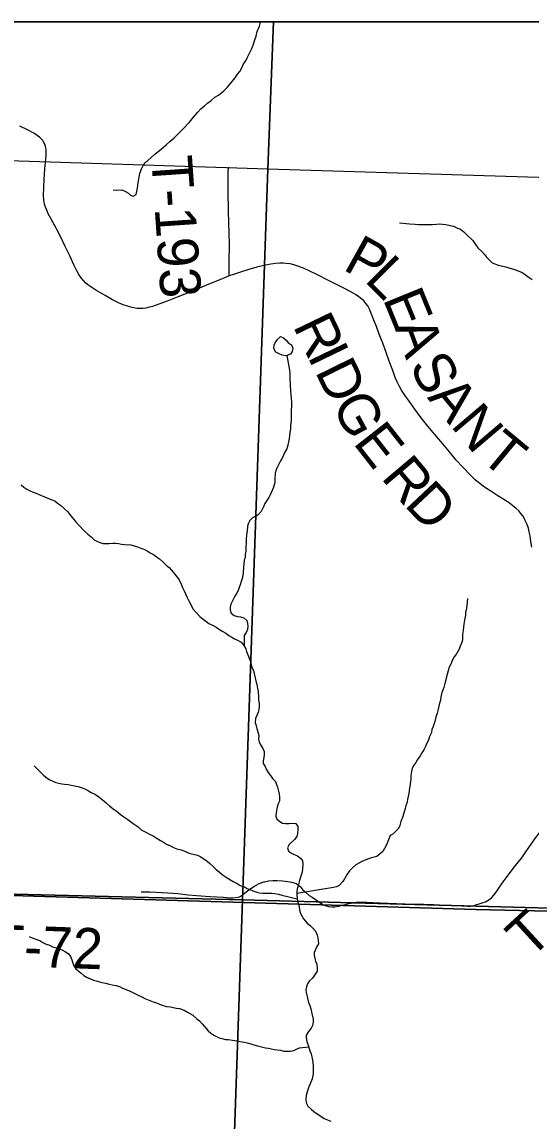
# Model space of a CAD drawing. Extents: x -3.3 to 34, y 0 to 56.8.
# Drawn here: x -0.562 to 0.148, y 33.346 to 34.877 of the extents above; entities that cross this region are included whole.
import ezdxf

# ---------------------------------------------------------------- set-up
doc = ezdxf.new("R2010")
doc.units = 0
for name, color, linetype in [('GM_X_Corporation', 7, 'Continuous'), ('GM_X_County_Road', 7, 'Continuous'), ('GM_X_Township_Road', 7, 'Continuous'), ('GM_X_Township_Road_Text', 7, 'Continuous'), ('GT_Project_Soil_Layers', 7, 'Continuous'), ('SH_Data', 7, 'Continuous'), ('SH_Masking', 7, 'Continuous')]:
    doc.layers.add(name, color=color, linetype=linetype)

msp = doc.modelspace()

# ---------------------------------------------------------------- linework, layer by layer
at = {"layer": 'GM_X_Corporation'}
for points in [[(1.8402, 34.8771), (-3.3039, 34.8771), (-3.3039, 33.7379), (-1.9559, 33.6976), (-1.4178, 33.6828), (-1.3158, 33.6798), (-1.2647, 33.6785), (-1.2619, 33.6785), (-1.2559, 33.6783), (-1.2477, 33.6781), (-0.684, 33.6635), (0.0711, 33.6404), (0.5386, 33.6297), (1.1691, 33.6097), (1.268, 33.607), (1.3813, 33.6045), (1.3939, 33.6042), (1.4033, 33.604), (1.5156, 33.6018), (1.5452, 33.6012), (1.798, 33.5922), (1.8165, 34.1713), (1.8337, 34.7226), (1.8394, 34.8565)], [(-0.2111, 34.8771), (-1.2253, 34.8771), (-1.231, 34.705), (-0.2186, 34.6726)], [(0.815, 34.8771), (-0.2111, 34.8771), (-0.2186, 34.6726), (0.8071, 34.6408)], [(-1.231, 34.705), (-0.2186, 34.6726), (-0.2543, 33.6541), (-1.2628, 33.6793)], [(0.8071, 34.6408), (0.7743, 33.6261), (-0.2543, 33.6541), (-0.2186, 34.6726)], [(-1.2628, 33.6793), (-0.2543, 33.6541), (-0.2878, 32.6826), (-1.3017, 32.7146)], [(-0.2543, 33.6541), (0.7743, 33.6261), (0.7357, 32.6242), (-0.2878, 32.6826)]]:
    msp.add_lwpolyline(points, close=True, dxfattribs=at)
msp.add_lwpolyline([(1.698, 31.5661), (1.7459, 32.363), (1.7461, 32.3685), (1.7485, 32.4264), (1.7493, 32.4459), (1.7554, 32.5941), (1.7581, 32.6599), (1.7584, 32.6672), (1.7602, 32.7115), (1.7831, 33.2694), (1.7901, 33.4394), (1.798, 33.5922), (1.5452, 33.6012), (1.5156, 33.6018), (1.4033, 33.604), (1.3939, 33.6042), (1.3813, 33.6045), (1.268, 33.607), (1.1691, 33.6097), (0.5386, 33.6297), (0.0711, 33.6404), (-0.684, 33.6635)], dxfattribs=at)
at = {"layer": 'GM_X_County_Road'}
msp.add_lwpolyline([(0.1491, 34.1456), (0.1479, 34.1532), (0.1467, 34.1613), (0.1456, 34.1667), (0.1443, 34.172), (0.1422, 34.1778), (0.14, 34.1827), (0.1384, 34.1859), (0.1365, 34.1891), (0.134, 34.1923), (0.1309, 34.1959), (0.1269, 34.1998), (0.1227, 34.2031), (0.1178, 34.2068), (0.1123, 34.2105), (0.1019, 34.217), (0.0932, 34.2225), (0.0883, 34.2256), (0.0817, 34.2299), (0.0767, 34.2339), (0.0708, 34.2387), (0.0675, 34.2418), (0.0637, 34.2456), (0.0534, 34.2563), (0.0439, 34.2668), (0.0342, 34.2782), (0.025, 34.2892), (0.0141, 34.3023), (0.0043, 34.314), (-0.0049, 34.3257), (-0.0141, 34.3376), (-0.0218, 34.3487), (-0.0277, 34.3571), (-0.0323, 34.3641), (-0.0354, 34.3693), (-0.0386, 34.3755), (-0.0411, 34.3818), (-0.0448, 34.3913), (-0.0495, 34.4044), (-0.0545, 34.4182), (-0.0586, 34.4295), (-0.0635, 34.4423), (-0.0675, 34.4527), (-0.071, 34.4618), (-0.0743, 34.4702), (-0.0771, 34.4768), (-0.0795, 34.4814), (-0.082, 34.4849), (-0.085, 34.4884), (-0.0879, 34.491), (-0.0918, 34.4941), (-0.0964, 34.4972), (-0.103, 34.5011), (-0.113, 34.5061), (-0.124, 34.5116), (-0.1354, 34.5174), (-0.1498, 34.5246), (-0.1614, 34.5304), (-0.1693, 34.5339), (-0.1782, 34.5374), (-0.1824, 34.5388), (-0.1876, 34.5399), (-0.1931, 34.5407), (-0.1976, 34.5409), (-0.2021, 34.541), (-0.2083, 34.5406), (-0.2144, 34.5398), (-0.2244, 34.5379), (-0.234, 34.5356), (-0.2453, 34.5323), (-0.2567, 34.5287), (-0.2668, 34.5253), (-0.2729, 34.5233), (-0.2858, 34.5179), (-0.3032, 34.5107), (-0.3214, 34.5031), (-0.3343, 34.4979), (-0.3453, 34.4935), (-0.3591, 34.4882), (-0.3707, 34.4837), (-0.3796, 34.4806), (-0.3854, 34.4792), (-0.389, 34.4784), (-0.3932, 34.4779), (-0.3969, 34.4777), (-0.4013, 34.478), (-0.408, 34.4792), (-0.4146, 34.481), (-0.4204, 34.4831), (-0.4271, 34.4859), (-0.4353, 34.49), (-0.4457, 34.496), (-0.4586, 34.5035), (-0.4643, 34.507), (-0.467, 34.5089), (-0.4696, 34.5109), (-0.4724, 34.5134), (-0.4757, 34.5168), (-0.4788, 34.5206), (-0.4821, 34.5254), (-0.4848, 34.5302), (-0.489, 34.5386), (-0.4944, 34.5503), (-0.5012, 34.5643), (-0.5074, 34.5771), (-0.5135, 34.5888), (-0.5214, 34.6033), (-0.5248, 34.6098), (-0.527, 34.6148), (-0.5287, 34.6192), (-0.53, 34.6233), (-0.5306, 34.6262), (-0.5309, 34.629), (-0.5313, 34.6351), (-0.5306, 34.6575), (-0.5297, 34.6724), (-0.5289, 34.6818), (-0.5279, 34.6909), (-0.5276, 34.6941), (-0.5277, 34.6971), (-0.528, 34.7), (-0.5288, 34.7036), (-0.5297, 34.7066), (-0.531, 34.7091), (-0.5326, 34.7118), (-0.5348, 34.7144), (-0.5372, 34.7166), (-0.5403, 34.719), (-0.545, 34.7221), (-0.5536, 34.7268), (-0.5643, 34.7321)], dxfattribs=at)
at = {"layer": 'GM_X_Township_Road'}
for points in [[(-0.2729, 34.5233), (-0.2726, 34.5426), (-0.2723, 34.5669), (-0.2726, 34.583), (-0.2733, 34.5979), (-0.2737, 34.6134), (-0.2739, 34.6416), (-0.2742, 34.6546), (-0.2742, 34.6625), (-0.2739, 34.6687), (-0.2732, 34.6747)], [(0.1397, 33.7195), (0.1449, 33.7272), (0.1547, 33.7407), (0.1599, 33.7473), (0.1638, 33.7533), (0.1682, 33.762), (0.1728, 33.7722), (0.1768, 33.7826), (0.1803, 33.7963), (0.183, 33.8094), (0.1886, 33.8493), (0.19, 33.8606), (0.1907, 33.8735), (0.1885, 33.9027), (0.1883, 33.9138), (0.1884, 33.9205), (0.1911, 33.9428), (0.1926, 33.9538), (0.1946, 33.9635), (0.1959, 33.9682), (0.1984, 33.9753)], [(0.0709, 33.6469), (0.0756, 33.6484), (0.0811, 33.6502), (0.0847, 33.6515), (0.0871, 33.6528), (0.0893, 33.6542), (0.0912, 33.6555), (0.0936, 33.6575), (0.0959, 33.6599), (0.0996, 33.6649), (0.1052, 33.6731), (0.1091, 33.6792), (0.1146, 33.6865), (0.1266, 33.7018), (0.1351, 33.7127), (0.1397, 33.7195)], [(-0.2559, 33.6597), (-0.2538, 33.6613), (-0.2494, 33.6647), (-0.2451, 33.6682), (-0.2374, 33.6733), (-0.2311, 33.6766), (-0.2245, 33.679)], [(-0.2245, 33.679), (-0.2235, 33.6793), (-0.2177, 33.6805), (-0.2117, 33.681), (-0.206, 33.6808), (-0.1984, 33.6803), (-0.1878, 33.6791), (-0.184, 33.6784), (-0.1795, 33.6767), (-0.176, 33.6745), (-0.1734, 33.6721), (-0.1703, 33.6686), (-0.167, 33.6653), (-0.161, 33.6603), (-0.1572, 33.6576), (-0.1524, 33.6545)], [(-0.3954, 33.6654), (-0.3834, 33.665), (-0.3581, 33.664), (-0.3514, 33.6635), (-0.3443, 33.6628), (-0.3298, 33.6612), (-0.3184, 33.6601), (-0.299, 33.6588), (-0.2805, 33.6576), (-0.2721, 33.6569), (-0.2675, 33.657), (-0.2635, 33.6574), (-0.2599, 33.6579), (-0.2566, 33.6591), (-0.2559, 33.6597)], [(-0.1524, 33.6545), (-0.1463, 33.6505), (-0.1411, 33.6473), (-0.1377, 33.6458), (-0.1341, 33.6449), (-0.1294, 33.6442), (-0.1252, 33.6444), (-0.1205, 33.6452), (-0.116, 33.6463), (-0.1054, 33.6491), (-0.1031, 33.6496), (-0.0956, 33.6507), (-0.0921, 33.6509), (-0.0913, 33.6509)], [(-0.0913, 33.6509), (-0.0881, 33.651), (-0.0806, 33.6506), (-0.0629, 33.6499), (-0.0393, 33.6489), (-0.0273, 33.6484), (-0.0157, 33.648), (-0.0014, 33.6478), (0.0127, 33.6476), (0.0285, 33.6468), (0.041, 33.6461), (0.052, 33.6456), (0.0597, 33.6452), (0.0639, 33.6453), (0.0672, 33.6457), (0.07, 33.6466), (0.0709, 33.6469)]]:
    msp.add_lwpolyline(points, dxfattribs=at)
at = {"layer": 'GT_Project_Soil_Layers'}
for points in [[(-0.4346, 34.6432), (-0.43, 34.6429), (-0.4221, 34.643), (-0.4183, 34.6412), (-0.4145, 34.6397), (-0.4102, 34.636), (-0.4064, 34.6342), (-0.4023, 34.6365), (-0.4012, 34.6411), (-0.4005, 34.6456), (-0.4002, 34.6498), (-0.3991, 34.6559), (-0.397, 34.6658), (-0.3948, 34.6723), (-0.3926, 34.6769), (-0.39, 34.6807), (-0.3821, 34.688), (-0.3761, 34.693), (-0.3716, 34.6965), (-0.3675, 34.7), (-0.3607, 34.7058), (-0.3555, 34.7104), (-0.3499, 34.715), (-0.345, 34.7197), (-0.3413, 34.7235), (-0.3375, 34.7277), (-0.3282, 34.7374), (-0.3226, 34.7443), (-0.3162, 34.7516), (-0.3121, 34.7562), (-0.3073, 34.7604), (-0.3031, 34.7639), (-0.2979, 34.7678), (-0.2926, 34.7724), (-0.2877, 34.7751), (-0.2802, 34.7813), (-0.275, 34.7863), (-0.2683, 34.794), (-0.2642, 34.7994), (-0.2612, 34.8043), (-0.2579, 34.8082), (-0.2556, 34.8124), (-0.2527, 34.8189), (-0.2497, 34.8227), (-0.2475, 34.8273), (-0.2438, 34.8346), (-0.2412, 34.8399), (-0.2394, 34.8449), (-0.2368, 34.8521), (-0.235, 34.8575), (-0.2336, 34.8636), (-0.2306, 34.8712), (-0.2288, 34.8769), (-0.2287, 34.8771)], [(-0.0351, 34.5973), (-0.0305, 34.5966), (-0.0214, 34.5959), (-0.0135, 34.5953), (-0.0089, 34.595), (-0.004, 34.595), (0.0021, 34.5947), (0.0108, 34.5949), (0.0165, 34.5953), (0.0207, 34.5958), (0.0248, 34.5954), (0.0294, 34.5947), (0.0355, 34.5933), (0.04, 34.5926), (0.0454, 34.59), (0.0496, 34.5882), (0.0542, 34.5845), (0.058, 34.5811), (0.0669, 34.5725), (0.0707, 34.5672), (0.0738, 34.5623), (0.0796, 34.5571), (0.0834, 34.553), (0.0861, 34.5492), (0.0938, 34.5417), (0.0976, 34.5403), (0.1022, 34.5384), (0.1129, 34.5359), (0.117, 34.5345), (0.122, 34.533), (0.1262, 34.5316), (0.13, 34.5305), (0.1357, 34.5279), (0.1399, 34.5253), (0.1441, 34.5219), (0.1495, 34.5182)], [(-0.1937, 34.4121), (-0.1987, 34.4127), (-0.2032, 34.4146), (-0.2078, 34.4172), (-0.2106, 34.4221), (-0.2102, 34.4266), (-0.208, 34.4308), (-0.205, 34.435), (-0.2013, 34.4389), (-0.1971, 34.4371), (-0.1933, 34.4337), (-0.1898, 34.4296), (-0.186, 34.4273), (-0.184, 34.4228), (-0.1851, 34.4182), (-0.1873, 34.4144), (-0.1937, 34.4121)], [(-0.1923, 34.4126), (-0.1906, 34.4022), (-0.1894, 34.3969), (-0.1885, 34.392), (-0.1881, 34.3871), (-0.188, 34.3791), (-0.1875, 34.373), (-0.1874, 34.3624), (-0.1869, 34.3586), (-0.1865, 34.3526), (-0.186, 34.3472), (-0.1859, 34.3408), (-0.1863, 34.337), (-0.1862, 34.3283), (-0.1864, 34.3222), (-0.1871, 34.3142), (-0.1874, 34.3096), (-0.1881, 34.3051), (-0.1888, 34.3009), (-0.1891, 34.2963), (-0.1898, 34.2921), (-0.1909, 34.2876), (-0.1924, 34.2822), (-0.1949, 34.2776), (-0.1968, 34.2734), (-0.199, 34.2696), (-0.2012, 34.2658), (-0.2053, 34.2574), (-0.2071, 34.2532), (-0.2086, 34.2486), (-0.2092, 34.2399), (-0.2092, 34.2353), (-0.211, 34.2288), (-0.2128, 34.2242), (-0.2154, 34.2185), (-0.2176, 34.2147), (-0.2228, 34.2063), (-0.225, 34.2017), (-0.2283, 34.1952), (-0.2324, 34.1902), (-0.2366, 34.1882), (-0.2403, 34.1863), (-0.2437, 34.1824), (-0.2459, 34.1786), (-0.247, 34.1748), (-0.2477, 34.1679), (-0.2484, 34.163), (-0.249, 34.1554), (-0.249, 34.1508), (-0.2493, 34.1463), (-0.2496, 34.1398), (-0.2503, 34.1353), (-0.2506, 34.1311), (-0.2517, 34.1273), (-0.2524, 34.1223), (-0.2527, 34.1174), (-0.2533, 34.1094), (-0.254, 34.1029), (-0.2562, 34.0976), (-0.2576, 34.093), (-0.2587, 34.0892), (-0.2602, 34.085), (-0.2624, 34.0808), (-0.2646, 34.077), (-0.2672, 34.0724), (-0.2706, 34.0659), (-0.2713, 34.0617), (-0.2712, 34.0579), (-0.27, 34.0533), (-0.2658, 34.05), (-0.2612, 34.0489), (-0.2567, 34.0482), (-0.2521, 34.0468), (-0.2483, 34.043), (-0.2471, 34.0392), (-0.2466, 34.0354), (-0.2473, 34.0309), (-0.2488, 34.0267), (-0.2518, 34.0225), (-0.2518, 34.0076)], [(-0.5625, 34.2322), (-0.5587, 34.2289), (-0.5548, 34.2262), (-0.5503, 34.224), (-0.5457, 34.2222), (-0.5415, 34.2204), (-0.5358, 34.2178), (-0.5308, 34.216), (-0.5247, 34.2134), (-0.5209, 34.2119), (-0.5159, 34.2101), (-0.5121, 34.2067), (-0.5079, 34.2038), (-0.5021, 34.1989), (-0.4979, 34.1952), (-0.4952, 34.1914), (-0.4914, 34.1865), (-0.4871, 34.1813), (-0.4833, 34.1768), (-0.474, 34.167), (-0.4698, 34.1633), (-0.4652, 34.1599), (-0.461, 34.1558), (-0.4572, 34.1536), (-0.453, 34.1518), (-0.4484, 34.1507), (-0.4438, 34.1504), (-0.4401, 34.1504), (-0.4351, 34.1509), (-0.4313, 34.1509), (-0.4268, 34.1506), (-0.4226, 34.1495), (-0.4188, 34.1492), (-0.4097, 34.1486), (-0.4006, 34.1457), (-0.3956, 34.1438), (-0.3918, 34.1428), (-0.3872, 34.1405), (-0.383, 34.1376), (-0.3784, 34.135), (-0.3742, 34.132)], [(-0.3742, 34.132), (-0.3696, 34.129), (-0.3646, 34.1245), (-0.36, 34.1197), (-0.3562, 34.1171), (-0.3531, 34.1133), (-0.3489, 34.1084), (-0.3458, 34.1039), (-0.3423, 34.0998), (-0.3396, 34.0937), (-0.3376, 34.0892), (-0.3353, 34.0847), (-0.3337, 34.0805), (-0.3317, 34.0764), (-0.3298, 34.0726), (-0.3282, 34.0688), (-0.3259, 34.0647), (-0.3235, 34.0594), (-0.3135, 34.0489), (-0.3089, 34.0452), (-0.3051, 34.0422), (-0.3009, 34.0389), (-0.2952, 34.0363), (-0.291, 34.0337), (-0.286, 34.0307), (-0.2814, 34.0277), (-0.2772, 34.0255), (-0.273, 34.0225), (-0.2692, 34.0199), (-0.2653, 34.0177), (-0.2611, 34.0159), (-0.2562, 34.0129), (-0.2523, 34.0084), (-0.2496, 34.0039), (-0.2484, 34.0001), (-0.2468, 33.9956), (-0.2449, 33.9907), (-0.2429, 33.9861), (-0.2409, 33.9778), (-0.239, 33.9737), (-0.2378, 33.9695), (-0.2365, 33.9631), (-0.2354, 33.9593), (-0.2341, 33.954), (-0.2333, 33.9487), (-0.2325, 33.9445), (-0.2316, 33.9366), (-0.2316, 33.932), (-0.2311, 33.9278), (-0.2311, 33.9233), (-0.2314, 33.9191), (-0.2321, 33.9153), (-0.2343, 33.9107), (-0.2361, 33.9065), (-0.2365, 33.9012), (-0.2353, 33.8966), (-0.2341, 33.8929), (-0.2313, 33.883), (-0.2316, 33.8781), (-0.2308, 33.8743), (-0.2288, 33.8701), (-0.2257, 33.8649), (-0.2241, 33.8607), (-0.2237, 33.8565), (-0.2244, 33.8524), (-0.2251, 33.8478), (-0.2251, 33.844), (-0.2227, 33.8398), (-0.2212, 33.8361), (-0.2184, 33.8316), (-0.215, 33.8274), (-0.2123, 33.8229), (-0.208, 33.8188), (-0.2065, 33.8146), (-0.2053, 33.8109), (-0.2045, 33.8071), (-0.2032, 33.8018), (-0.2024, 33.7972), (-0.2027, 33.7915), (-0.2042, 33.7877), (-0.2056, 33.7831), (-0.2071, 33.7755), (-0.2078, 33.7706), (-0.2062, 33.7664), (-0.2023, 33.763), (-0.1985, 33.7608), (-0.194, 33.7605), (-0.1894, 33.7606), (-0.1849, 33.761), (-0.1799, 33.7603), (-0.1772, 33.7562), (-0.1768, 33.752), (-0.1775, 33.7463), (-0.1785, 33.7425), (-0.1815, 33.7379), (-0.189, 33.731), (-0.1912, 33.7264), (-0.19, 33.7218), (-0.1858, 33.7192), (-0.182, 33.7174), (-0.1774, 33.7155)], [(0.0596, 34.0739), (0.0589, 34.0686), (0.0586, 34.0644), (0.0579, 34.0606), (0.0568, 34.0545), (0.0565, 34.0507), (0.0551, 34.0439), (0.0544, 34.0382), (0.0537, 34.0344), (0.0534, 34.0294), (0.0523, 34.0237), (0.0524, 34.0157), (0.0513, 34.0115), (0.0495, 34.0073), (0.0477, 34.0035), (0.044, 33.997), (0.041, 33.9924), (0.0388, 33.9886), (0.0362, 33.9825), (0.0336, 33.9775), (0.0325, 33.9729), (0.0307, 33.9664), (0.0296, 33.9623), (0.0282, 33.9573), (0.0264, 33.9501), (0.0238, 33.9428), (0.0224, 33.9371), (0.0217, 33.9318), (0.0203, 33.9279), (0.0195, 33.9241), (0.0181, 33.9177), (0.017, 33.9139), (0.0152, 33.9085), (0.0138, 33.9024), (0.0116, 33.8956), (0.0098, 33.8913), (0.0091, 33.8872), (0.0065, 33.8814), (0.005, 33.8765), (0.0028, 33.8723), (0.001, 33.8677), (-0.0012, 33.8631), (-0.0042, 33.8589), (-0.0064, 33.8547), (-0.0101, 33.8497), (-0.0124, 33.8455), (-0.0153, 33.8416), (-0.0176, 33.8374), (-0.0186, 33.8328), (-0.0193, 33.8275), (-0.0196, 33.8222), (-0.021, 33.8123), (-0.0217, 33.8062), (-0.0224, 33.802), (-0.0238, 33.7963), (-0.0249, 33.7887), (-0.0263, 33.7849), (-0.0274, 33.7811), (-0.0292, 33.775), (-0.031, 33.7689), (-0.0332, 33.7631), (-0.035, 33.7574), (-0.0369, 33.7536), (-0.0403, 33.7498), (-0.0447, 33.7455), (-0.0485, 33.7436), (-0.0503, 33.739), (-0.0514, 33.7352), (-0.0533, 33.7306), (-0.0562, 33.7256), (-0.0584, 33.7214), (-0.0667, 33.7144), (-0.0705, 33.7133), (-0.0742, 33.7124), (-0.0784, 33.7112), (-0.0867, 33.7081), (-0.0912, 33.7057), (-0.0961, 33.7026), (-0.1006, 33.6988), (-0.1051, 33.6945), (-0.1081, 33.6896), (-0.1118, 33.6834), (-0.1144, 33.6796), (-0.1192, 33.6742), (-0.123, 33.6723), (-0.1275, 33.6711), (-0.1786, 33.6627)], [(-0.5443, 33.8406), (-0.5393, 33.8358), (-0.5358, 33.832), (-0.532, 33.8283), (-0.5281, 33.8249), (-0.5235, 33.8219), (-0.5144, 33.8175), (-0.5102, 33.8164), (-0.506, 33.8157), (-0.5022, 33.8154), (-0.4969, 33.8147), (-0.4931, 33.814), (-0.4878, 33.813), (-0.4832, 33.8119), (-0.4775, 33.8101), (-0.4729, 33.8082), (-0.4687, 33.806), (-0.4649, 33.8038), (-0.4599, 33.8012), (-0.4561, 33.799), (-0.45, 33.7945), (-0.4435, 33.7889), (-0.4396, 33.7852), (-0.4343, 33.7807), (-0.4304, 33.7781), (-0.4247, 33.7736), (-0.4197, 33.7699), (-0.414, 33.7658), (-0.4101, 33.7632), (-0.4063, 33.7602), (-0.3994, 33.7557), (-0.3952, 33.7516), (-0.3898, 33.7486), (-0.383, 33.7453), (-0.3788, 33.7431), (-0.3746, 33.7405), (-0.3684, 33.7368), (-0.3642, 33.7346), (-0.36, 33.7316), (-0.3543, 33.7294), (-0.3501, 33.7272), (-0.3455, 33.7253), (-0.3398, 33.7235), (-0.336, 33.7221), (-0.331, 33.7202), (-0.3269, 33.7188), (-0.317, 33.7162), (-0.3124, 33.714), (-0.3036, 33.7081), (-0.2997, 33.7047), (-0.2948, 33.7006), (-0.2913, 33.6969), (-0.2863, 33.6924), (-0.2825, 33.6894), (-0.2756, 33.6849), (-0.2672, 33.6797), (-0.2614, 33.6768), (-0.2576, 33.6742), (-0.2515, 33.672), (-0.2477, 33.6697), (-0.2385, 33.6661), (-0.234, 33.6646), (-0.2302, 33.6639), (-0.226, 33.6632), (-0.2131, 33.6634), (-0.2089, 33.6631), (-0.204, 33.662), (-0.1994, 33.6605), (-0.1778, 33.6556)], [(-0.1774, 33.7155), (-0.1732, 33.7122), (-0.1705, 33.7084), (-0.1701, 33.7043), (-0.1707, 33.6963), (-0.1714, 33.6913), (-0.1729, 33.6871), (-0.1747, 33.681), (-0.1758, 33.6772), (-0.1765, 33.6734), (-0.1779, 33.6696), (-0.1786, 33.6654), (-0.1786, 33.6605), (-0.1773, 33.6521), (-0.1761, 33.6483), (-0.1753, 33.6438), (-0.1741, 33.6377), (-0.1729, 33.634), (-0.169, 33.6276), (-0.164, 33.6215), (-0.1598, 33.6182), (-0.1559, 33.6148), (-0.1525, 33.6103), (-0.1501, 33.605), (-0.1489, 33.6013), (-0.1485, 33.5975), (-0.1484, 33.5929), (-0.1503, 33.5891), (-0.1525, 33.5849), (-0.154, 33.5807), (-0.1543, 33.5769), (-0.1535, 33.5723), (-0.1523, 33.5685), (-0.1507, 33.5644), (-0.1502, 33.5587), (-0.1502, 33.5545), (-0.1528, 33.5503), (-0.1565, 33.5449), (-0.1606, 33.5411), (-0.1636, 33.5372), (-0.1651, 33.533), (-0.1658, 33.5288), (-0.1653, 33.5251), (-0.1645, 33.5213), (-0.1637, 33.5171), (-0.1621, 33.511), (-0.1605, 33.5069), (-0.1589, 33.502), (-0.1573, 33.4959), (-0.1557, 33.4876), (-0.1557, 33.4834), (-0.1567, 33.4792), (-0.1586, 33.4754), (-0.1623, 33.4704), (-0.1653, 33.4654), (-0.1652, 33.4616), (-0.1644, 33.4567), (-0.1624, 33.4514), (-0.1604, 33.4435), (-0.1585, 33.4397), (-0.1569, 33.4329), (-0.156, 33.428), (-0.1556, 33.4219), (-0.1555, 33.4162), (-0.1558, 33.4116), (-0.1568, 33.4048), (-0.1598, 33.3975), (-0.1616, 33.3937), (-0.1631, 33.3895), (-0.1649, 33.3834), (-0.166, 33.3784), (-0.1659, 33.3743), (-0.1647, 33.3705), (-0.1631, 33.3667), (-0.1585, 33.3622), (-0.1547, 33.3592), (-0.1501, 33.3559), (-0.1448, 33.3525), (-0.1402, 33.3495), (-0.131, 33.3455)], [(-0.5516, 33.6028), (-0.5471, 33.601), (-0.5421, 33.5991), (-0.5368, 33.5973), (-0.5326, 33.5947), (-0.5276, 33.5925), (-0.523, 33.5911), (-0.5188, 33.5888), (-0.5135, 33.5874), (-0.5059, 33.5845), (-0.5009, 33.5815), (-0.4971, 33.5793), (-0.494, 33.5751), (-0.492, 33.5706), (-0.4897, 33.563), (-0.4862, 33.5578), (-0.4793, 33.5522), (-0.4751, 33.5488), (-0.4708, 33.5458), (-0.4667, 33.5444), (-0.4617, 33.5422), (-0.4564, 33.5407), (-0.4503, 33.5389), (-0.445, 33.5378), (-0.44, 33.5368), (-0.4358, 33.5357), (-0.4305, 33.5346), (-0.4256, 33.5332), (-0.4214, 33.531), (-0.4107, 33.5266), (-0.4053, 33.524), (-0.3988, 33.521), (-0.3946, 33.5188), (-0.3901, 33.5166), (-0.3855, 33.5148), (-0.3786, 33.5118), (-0.3741, 33.5107), (-0.3699, 33.5089), (-0.366, 33.5074), (-0.36, 33.5056), (-0.3546, 33.5049), (-0.3508, 33.5042), (-0.3463, 33.5031), (-0.3417, 33.5025), (-0.3356, 33.5003), (-0.331, 33.4977), (-0.3234, 33.4932), (-0.318, 33.4884), (-0.3142, 33.4857), (-0.3103, 33.4812), (-0.3069, 33.4775), (-0.3022, 33.4715), (-0.2984, 33.4681), (-0.2942, 33.4655), (-0.2866, 33.4618), (-0.2827, 33.4607), (-0.2778, 33.4597), (-0.274, 33.4593), (-0.2649, 33.458), (-0.2611, 33.4576), (-0.2573, 33.4569), (-0.252, 33.4559), (-0.2478, 33.4548), (-0.2425, 33.4533), (-0.2383, 33.4522), (-0.2333, 33.4508), (-0.2219, 33.4479), (-0.2181, 33.4472), (-0.2135, 33.4465), (-0.2097, 33.4454), (-0.2052, 33.4451), (-0.201, 33.4444), (-0.1964, 33.4433), (-0.1919, 33.443), (-0.1873, 33.4431), (-0.1828, 33.4443), (-0.179, 33.4462), (-0.1749, 33.4478), (-0.1619, 33.4492)]]:
    msp.add_lwpolyline(points, dxfattribs=at)
at = {"layer": 'SH_Data'}
msp.add_line((-3.3039, 34.8771), (3.4961, 34.8771), dxfattribs=at)

# ---------------------------------------------------------------- texts
at = {"layer": 'GM_X_Township_Road_Text'}
for s, height, rotation, p in [('T-193', 0.05682, 273.9259, (-0.3814, 34.689)), ('T', 0.0568, 42.5842, (0.1465, 33.5704)), ('T-72', 0.05682, 357.8787, (-0.6058, 33.563))]:
    msp.add_text(s, height=height, rotation=rotation, dxfattribs=at).set_placement(p)
at = {"layer": 'SH_Masking'}
for s, rotation, p in [('P', 330.8439, (-0.1157, 34.5329)), ('L', 314.8697, (-0.0856, 34.5167)), ('E', 292.189, (-0.0589, 34.4916)), ('R', 295.7516, (-0.1845, 34.4538)), ('A', 290.1493, (-0.043, 34.4527)), ('I', 295.8192, (-0.1642, 34.4117)), ('D', 296.1676, (-0.1538, 34.3904)), ('S', 297.6403, (-0.0225, 34.3983)), ('G', 298.395, (-0.1307, 34.3434)), ('A', 309.7664, (0.0026, 34.3535)), ('N', 310.282, (0.0349, 34.3146)), ('E', 308.1437, (-0.1011, 34.2906)), ('T', 320.3199, (0.0749, 34.2688)), ('R', 310.2351, (-0.0622, 34.242)), ('D', 313.2313, (-0.0299, 34.2039))]:
    msp.add_text(s, height=0.0568, rotation=rotation, dxfattribs=at).set_placement(p)

doc.saveas('drawing.dxf')
